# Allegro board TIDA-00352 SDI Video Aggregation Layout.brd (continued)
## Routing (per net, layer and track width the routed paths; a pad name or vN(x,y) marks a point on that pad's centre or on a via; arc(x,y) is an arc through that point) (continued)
I2C_STATUS1: length 183.7
  TOP w0.254: U42.18 101.32,24.75 v1(101.97,25.4)
  L14_SIG3 w0.152: v1(101.97,25.4) 101.97,25.83 101.98,25.84 101.98,29.21 96.52,34.67 84.99,34.67 84.07,35.59 84.07,44.07 76.2,51.94 71.12,51.94 62.48,60.58 62.48,101.35 53.59,110.24 53.59,115.06 50.42,118.24 41.27,118.24 40.89,118.62 40.89,118.63 35.76,123.76 35.76,142.71 26.93,151.54 v1(17.53,151.54)
I2C_SYNCN: length 125.3
  TOP w0.254: U42.22 99.32,25.27 v1(98.68,25.91)
  L14_SIG3 w0.152: v1(44.31,110.72) 44.92,110.11 48.9,110.11 51.69,107.31 53.21,107.31 60.45,100.08 60.45,59.56 70.1,49.91 74.8,49.91 79.83,44.88 79.83,30.15 81.28,28.7 97.54,28.7 98.68,27.56 v1(98.68,25.91)
INA0N: length 76.9
  BOTTOM w0.114: v2(49.09,68.16) 48.69,67.76 48.69,65.58 53.64,60.63 56.1,60.63 70.13,46.61 103.47,46.61 107.59,50.73 107.59,50.9 107.59,51.09 107.74,51.23 108.09,51.23 108.24,51.38 108.24,51.54 108.24,51.73 108.38,51.88 108.74,51.88 108.88,52.03 108.88,52.19 108.88,52.38 109.03,52.53 109.38,52.53 109.56,52.7 109.56,52.7 109.77,52.91 109.77,54.49 C224.1
INA0N_CONNECTOR: length 2.5
  BOTTOM w0.254: v1(109.22,57.78) 109.22,55.24
INA0P: length 76.9
  BOTTOM w0.114: v2(48.09,68.16) 48.5,67.76 48.5,65.5 53.56,60.44 56.02,60.44 70.05,46.42 103.55,46.42 109.75,52.62 109.75,52.62 109.96,52.83 109.96,54.51 C222.1
INA0P_CONNECTOR: length 2.5
  BOTTOM w0.254: v1(110.49,57.78) 110.49,55.24
INA1N: length 61.7
  BOTTOM w0.114: C220.1 99.6,54.5 99.6,53.67 99.28,53.35 99.02,53.35 98.82,53.16 98.82,52.9 98.63,52.71 98.37,52.71 98.18,52.52 98.18,52.25 94.94,49.02 70,49.02 53.64,65.38 53.64,67.73 52.62,68.76 51.5,68.76 v2(51.09,69.16)
INA1N_CONNECTOR: length 2.5
  BOTTOM w0.254: v1(99.06,57.78) 99.06,55.24
INA1P: length 61.7
  BOTTOM w0.114: C218.1 99.79,54.5 99.79,53.59 95.02,48.83 69.92,48.83 53.45,65.3 53.45,67.66 52.54,68.57 51.5,68.57 v2(51.09,68.16)
INA1P_CONNECTOR: length 2.5
  BOTTOM w0.254: v1(100.33,57.78) 100.33,55.24
INA2N: length 45.5
  BOTTOM w0.114: C216.1 84.39,54.47 84.39,53.86 84.22,53.69 84.03,53.69 83.97,53.69 83.77,53.49 83.77,53.3 83.77,53.24 83.57,53.04 83.38,53.04 83.32,53.04 83.12,52.84 83.12,52.65 83.12,52.59 81.58,51.05 70.64,51.05 56.31,65.38 56.31,66.8 53.35,69.77 50.49,69.77 v2(50.09,70.16)
INA2N_CONNECTOR: length 2.5
  BOTTOM w0.254: v1(83.82,57.78) 83.82,55.24
INA2P: length 45.5
  BOTTOM w0.114: v2(50.09,69.16) 50.51,69.58 53.27,69.58 56.12,66.73 56.12,65.3 70.56,50.86 81.66,50.86 84.58,53.78 84.58,54.53 C214.1
INA2P_CONNECTOR: length 2.5
  BOTTOM w0.254: v1(85.09,57.78) 85.09,55.24
INA3N: length 33.3
  BOTTOM w0.114: C212.1 74.2,54.5 74.2,53.73 73.63,53.16 73.29,53.16 73.16,53.29 72.83,53.29 72.7,53.16 71.91,53.16 71.62,53.45 71.62,53.64 71.62,53.79 71.47,53.94 71.13,53.94 64.6,60.47 64.6,61.64 54.48,71.75 51.5,71.75 v2(51.09,72.16)
INA3N_CONNECTOR: length 2.5
  BOTTOM w0.254: v1(73.66,57.78) 73.66,55.24
INA3P: length 33.3
  BOTTOM w0.114: C210.1 74.39,54.5 74.39,53.65 73.71,52.97 71.83,52.97 64.41,60.39 64.41,61.56 54.4,71.56 51.5,71.56 v2(51.09,71.16)
INA3P_CONNECTOR: length 2.5
  BOTTOM w0.254: v1(74.93,57.78) 74.93,55.24
JTAG_LS_EN: length 5.6
  BOTTOM w0.254: R270.2 53.95,12.83 53.92,12.86 R647.2 51.02,12.86 50.34,13.54 v1(50.34,14.61)
JTAG_LS_VCCB: length 6.7
  TOP w0.254: v1(55.5,10.64) 55.5,10.11 55.54,10.07 U40.19
  L3_SIG2 w0.152: v1(60.07,11.89) 58.83,10.64 v1(55.5,10.64)
JTAG_LS_VCCB_3V: length 1.2
  BOTTOM w0.254: R269.2 JMP62.2
LOSA: length 127.4
  L3_SIG2 w0.152: v2(43.09,72.16) 42.55,71.61 42.55,67.06 47.12,62.48 56.85,62.48 63.58,55.75 79.5,55.75 89.47,45.78 89.47,35.24 88.52,34.29 87.38,34.29 86.36,33.27 86.36,11.18 88.14,9.4 88.14,4.95 89.15,3.94 90.93,3.94 91.57,4.57 91.57,5.08 92.52,6.03 99.63,6.03 JMP48.1
  BOTTOM w0.254: R276.1 100.65,12.19 99.69,11.24 99.69,7.18 100.65,6.22 R273.1 JMP48.1
LOSA_G: length 26.6
  L14_SIG3 w0.152: v1(100.71,7.37) 91.01,17.07 91.01,19.08 89.85,20.24 v1(80.58,20.24)
LOSB: length 127.5
  L14_SIG3 w0.152: v2(44.09,77.16) 43.65,77.6 43.08,77.6 42.69,77.99 42.69,79.33 42.97,79.62 51.21,79.62 51.56,79.27 51.56,64.71 62.5,53.77 62.5,19.29 65.53,16.26 73.66,16.26 83.94,5.98 84.83,5.98 85.47,5.33 85.47,4.84 86.34,3.98 97.19,3.98 98.17,4.95
  BOTTOM w0.254: R283.1 98.17,10.67 97.28,9.78 97.28,7.05 98.11,6.22 R279.1 98.17,4.95
LOSB_G: length 26.9
  L14_SIG3 w0.152: v1(76.64,20.24) 77.32,19.56 85.98,19.56 v1(98.17,7.37)
LS_EN_FETD: length 13.8
  TOP w0.254: Q100.3 122.68,16.97 122.94,17.23 v1(123.44,17.23)
  L3_SIG2 w0.152: v1(123.44,17.23) 123.44,18.31 123.52,18.39 123.52,22.91 119.76,26.67 v1(118.49,26.67)
LS_OK_IN_A_CONNECTOR: length 205.9
  TOP w0.254: JMP61.3 84.2,5.97
  L3_SIG2 w0.152: JMP61.3 84.2,5.97 81.01,9.16 81.01,33.89 82.32,35.2 83.72,35.2 88.14,39.62 88.52,40.01 88.52,45.59 78.87,55.24 62.99,55.24 56.77,61.47 46.99,61.47 41.53,66.93 41.53,68.59 v2(42.09,69.16)
  L14_SIG3 w0.152: v1(118.11,57.78) 118.11,54.4 115.35,51.64 115.35,30.44 120.02,25.78 120.02,14.73 122.3,12.45 122.3,11.56 121.28,10.54 121.28,10.53 114.27,3.52 85.64,3.52 JMP61.3
  BOTTOM w0.254: R532.1 84.26,12.19 83.69,11.62 83.69,10.1 84.26,9.53 R619.1 84.33,8.89 83.57,8.13 83.57,6.79 84.14,6.22 R254.2 JMP61.3
LS_OK_IN_B_CONNECTOR: length 209.9
  L3_SIG2 w0.152: v1(118.11,69.22) 116.59,70.74 98.42,70.74 89.28,79.88 42.93,79.88 42.55,79.5 42.55,78.87 42.8,78.61 43.23,78.61 43.68,78.16 v2(44.09,78.16)
  L14_SIG3 w0.152: v1(118.11,69.22) 118.87,69.98 121.92,69.98 122.56,69.34 122.56,62.48 121.41,61.34 121.41,56.01 116.95,51.55 116.95,37.85 116.97,37.83 116.97,30.48 120.99,26.46 120.99,15.4 123.27,13.12 123.27,11.11 114.74,2.59 102.92,2.59 101.31,0.98 81.71,0.98 80.68,2.01 80.68,2.82 81.66,3.8 JMP61.5
  BOTTOM w0.254: JMP61.5 R255.2 81.6,6.22 81.03,6.79 81.03,8.95 81.6,9.53 ; 81.6,9.53 81.03,10.1 81.03,11.75 81.6,12.32 R533.1 ; 81.6,9.53 R620.1
LS_OK_OUT_A_CONNECTOR: length 214.1
  L3_SIG2 w0.152: 84.2,2.41 85.18,1.44 102.78,1.44 110.11,8.76 114.3,8.76 114.72,9.18 114.73,9.18 114.99,9.44 114.99,9.8 114.94,9.85 114.94,14.1 111.89,17.14 111.89,25.53 110.46,26.95 110.46,32.31 110.74,32.59 110.74,39.78 109.86,40.66 109.86,49.38 112.8,52.32 116.59,52.32 120.65,56.39 v1(120.65,57.78) 121.16,58.29 121.16,72.64 117.02,76.78 102.03,76.78 94.23,84.58 v1(86.49,84.58) ; v2(43.09,71.16) 43.55,71.62 43.55,73.19 43.92,73.57 52.16,73.57 v2(52.27,73.68) 62.12,73.68 62.87,74.42 v1(86.49,74.42)
  L14_SIG3 w0.152: v1(86.49,74.42) v1(86.49,84.58)
  BOTTOM w0.254: 84.2,2.41 85.47,3.68 85.47,9.91 85.85,10.29 R286.1 R274.1
LS_OK_OUT_A_G: length 21.2
  L14_SIG3 w0.152: v1(87.07,13.34) 82.12,18.29 70.72,18.29 v1(68.77,20.24)
  BOTTOM w0: v1(87.07,13.34) R274.2
LS_OK_OUT_B_CONNECTOR: length 211.6
  L3_SIG2 w0.152: v1(54.48,82.42) 66.42,82.42 67.06,81.79 91.57,81.79 101.09,72.26 118.87,72.26 120.65,70.48 v1(120.65,69.22) ; v2(43.09,75.16) 43.58,74.68 v1(54.33,74.68)
  L14_SIG3 w0.152: v1(54.33,74.68) 54.33,75.11 54.48,75.27 v1(54.48,82.42) ; JMP61.6 82.64,1.44 101.12,1.44 102.74,3.06 114.03,3.06 114.05,3.05 114.55,3.05 122.02,10.52 122.81,11.3 122.81,12.93 120.52,15.21 120.52,26.04 116.49,30.06 116.49,51.85 120.02,55.37 120.02,68.58 v1(120.65,69.22)
  BOTTOM w0.254: JMP61.6 80.39,3.68 80.39,6.35 79.88,6.86 R287.1 R277.1
LS_OK_OUT_B_G: length 16.5
  L14_SIG3 w0.152: v1(64.83,20.24) 67.41,17.65 74.3,17.65 v1(78.49,13.46)
MAIN_/RST: length 8.1
  L3_SIG2 w0.152: v1(76.34,107.57) 77.48,107.57 78.99,109.09 v1(78.99,112.39)
  BOTTOM w0.254: R243.2 v1(76.34,107.57)
MAIN_/RST_B: length 2.7
  BOTTOM w0.254: U38.4 77.4,113.34 77.6,113.54 R259.1
MAIN_/RST_C:
  vias: v1(77.4,114.51)
MAIN_/RST_L:
  vias: v1(77.47,116.15)
MAIN_RESET: length 22.8
  L3_SIG2 w0.152: v1(70.48,107.57) 70.48,106.43 69.5,105.44 64.86,105.44 63.01,107.29 63.01,108.44 58.42,113.03 58.42,114.87 v1(56.91,116.38)
  BOTTOM w0.254: v1(56.91,116.38) 56.91,117.61 R724.1
MAIN_RESET_HS: length 8.1
  BOTTOM w0.254: R243.1 R244.1 R241.2 ; R243.1 72.64,107.57 72.64,107.57 R486.1 ; R243.1 U36.4
MAIN_RST: length 3
  BOTTOM w0.254: U37.3 R244.2 74.42,109.88 R258.2
MAIN_RST_B: length 1.6
  BOTTOM w0.254: U38.6 75.5,111.38 75.56,111.32 R258.1
MAIN_RST_C:
  vias: v1(75.5,114.51)
MAIN_RST_DIR: length 5.2
  BOTTOM w0.254: v1(75.95,103.38) R245.2 75.95,105.11 75.75,105.31 74.07,105.31 73.8,105.04 U36.5
MAIN_RST_L:
  vias: v1(75.51,116.15)
MAIN_RST_SIGNAL: length 6.4
  BOTTOM w0.254: R466.2 U37.4 78.74,110.03 79.1,110.38 R465.2 79.1,111.25 79.53,111.69 79.53,111.96 v1(81.1,113.54)
MDC: length 85.2
  L14_SIG3 w0.152: 43.61,75.62 v2(43.59,75.64) 38.8,75.64 18.6,55.44 18.6,13.65 20.12,12.12 22.92,12.12 23.62,12.83 25.21,12.83 v1(25.84,12.2)
  BOTTOM w0.152: R294.1 43.59,76.1 v2(43.59,75.64)
  BOTTOM w0.254: R289.1 25.84,13.25 v1(25.84,12.2)
MDC_B2B_CON: length 140.3
  L3_SIG2 w0.152: v1(74.93,64.14) 74.32,64.74 64.29,64.74 63.37,65.66 v1(58.17,65.66)
  L14_SIG3 w0.152: v1(58.17,65.66) 58.17,82.68 57.4,83.44 27.56,83.44 9.91,65.79 9.91,24.38 11.43,22.86 11.43,21.72 13.08,20.07 13.08,17.79 v1(13.6,17.27)
MDC_BYPASS: length 20.9
  L14_SIG3 w0.152: v1(24.69,12.2) 24.16,11.67 15.3,11.67 9.65,17.31 9.65,18.39 8.87,19.18 8.26,19.18 v1(7.87,19.56)
MDC_CON: length 3.3
  BOTTOM w0.254: JMP50.2 R291.1 R299.1
MDC_DUT:
  vias: v2(44.09,76.16)
MDC_HDR: length 17.5
  L14_SIG3 w0.152: 4.57,12.32 3.17,13.72 3.17,19.05 4.44,20.32 8.89,20.32 9.83,19.38 11.87,19.38 v1(12.31,19.81)
MDC_LS_BY: length 13.2
  L14_SIG3 w0.152: v1(18.16,7.11) 17.73,7.11 14.55,10.29 14.55,11.07 9.74,15.88 v1(9.02,15.88)
MDC_OUT_POST_LS: length 102.5
  TOP w0.254: K2.3 v1(13.6,18.54)
  L3_SIG2 w0.152: v1(13.6,18.54) 13.6,19.67 12.7,20.57 12.7,27.37 16.13,30.8 16.13,81.09 19.62,84.58 42.74,84.58 44.2,83.12 v1(44.2,81.53)
  BOTTOM w0.114: v1(44.2,81.53) 44.2,80.9 43.56,80.26 R294.2
MDC_POST_LS: length 2.1
  BOTTOM w0.254: v1(25.84,11.05) 25.84,10.55 26.09,10.29 U43.3
MDC_PRE_LS: length 15.3
  BOTTOM w0.254: R637.2 19.3,3.43 20.83,1.91 25.63,1.91 26.09,2.37 U43.18 v1(26.09,4.58) 26,4.67 26,4.81 25.67,5.14 24.82,5.14 24.42,4.74 R307.1
MDC_USB: length 7.7
  TOP w0.254: J101.12 v1(17.98,10.98)
  BOTTOM w0.254: R308.1 20.44,8.64 18.45,10.64 18.32,10.64 v1(17.98,10.98)
MDIO: length 85
  L14_SIG3 w0.152: v1(26.87,12.2) 25.1,13.97 23.75,13.97 22.99,13.21 20.57,13.21 19.68,14.1 19.68,54.99 39.37,74.68 44.46,74.68 44.61,74.83 v2(44.61,75.64)
  BOTTOM w0.152: R292.1 44.58,76.1 44.58,75.68 v2(44.61,75.64)
  BOTTOM w0.254: R288.2 26.87,13.25 v1(26.87,12.2)
MDIO_B2B_CON: length 139.4
  L3_SIG2 w0.152: v1(57.91,64.77) 63.5,64.77 64.14,64.14 v1(72.39,64.14)
  L14_SIG3 w0.152: v1(13.73,15.11) 14.35,15.73 14.35,19.49 11.94,21.91 11.94,23.11 10.41,24.64 10.41,65.53 27.79,82.91 57.17,82.91 57.66,82.42 57.66,65.46 57.91,65.2 v1(57.91,64.77)
MDIO_B2B_R: length 10.3
  L3_SIG2 w0.152: v1(15.48,13.84) 16,14.36 16,16.62 v1(15.35,17.27)
  BOTTOM w0.254: Q103.3 R641.2 17.43,19.35 v1(15.35,17.27)
MDIO_B2B_R_INV: length 4.5
  BOTTOM w0.254: Q103.1 21.64,22.29 21.65,22.29 R642.2 Q104.3
MDIO_B2B_RELAY: length 130.6
  TOP w0.254: SW11.15 v1(114.55,9.62)
  L3_SIG2 w0.152: v1(92.84,26.8) 91.82,25.78 88.14,25.78 v1(87.76,26.16) ; v1(74.04,26.16) 74.04,19.05 72.26,17.27 v1(72.26,6.48)
  L14_SIG3 w0.152: v1(114.55,9.62) 103.16,9.62 99.06,13.72 99.06,18.8 98.3,19.56 96.9,19.56 96.27,18.92 93.73,18.92 92.84,19.81 v1(92.84,26.8) ; v1(87.76,26.16) v1(74.04,26.16) ; v1(72.26,6.48) 71.88,6.86 44.96,6.86 36.53,15.29 36.53,18.1 33.41,21.21 31.24,21.21 v1(29.21,23.24)
  BOTTOM w0.254: v1(29.21,23.24) Q104.1
MDIO_BYPASS: length 26.5
  L14_SIG3 w0.152: v1(7.87,14.73) 13.84,8.76 15.24,8.76 17.53,6.48 20.83,6.48 21.84,7.49 24.26,7.49 27.3,10.54 27.3,11.49 v1(28.01,12.2)
MDIO_CON: length 3.3
  BOTTOM w0.254: R298.1 R290.1 JMP50.4
MDIO_CON_R: length 17.3
  L3_SIG2 w0.152: v1(10.55,19.81) 10.99,19.38 10.99,14.15 v1(10.68,13.84)
  BOTTOM w0.254: R644.2 2.57,23.75 Q101.3 3.95,22.34 4.95,21.34 8.25,21.34 9.78,19.81 v1(10.55,19.81)
MDIO_CON_R_INV: length 8.3
  BOTTOM w0.254: Q101.1 6,24.7 6.95,23.75 Q102.3 8.53,22.72 9.4,21.84 R645.2
MDIO_CON_RELAY: length 147.4
  TOP w0.254: SW11.17 v1(115.82,9.62)
  L3_SIG2 w0.152: v1(72.9,26.8) 72.9,22.48 72.14,21.72 72.14,18.92 71.5,18.29 v1(71.5,5.46)
  L14_SIG3 w0.152: v1(12.19,24.64) 17.53,19.3 v1(18.03,19.3) ; v1(115.82,9.62) 115.37,9.16 101.55,9.16 91.47,19.24 91.47,20.66 90.04,22.09 90.04,24.77 89.41,25.4 v1(89.41,26.8) v1(72.9,26.8) ; v1(71.5,5.46) 70.9,6.06 44.74,6.06 36.07,14.73 36.07,17.91 34.67,19.3 v1(20.83,19.3)
  BOTTOM w0.152: v1(20.83,19.3) v1(18.03,19.3)
  BOTTOM w0.254: Q102.1 11.23,24.7 11.29,24.64 v1(12.19,24.64)
MDIO_DUT:
  vias: v2(45.09,76.16)
MDIO_HDR: length 9
  BOTTOM w0.254: v1(12.43,12.57) 9.64,9.78 JMP103.1
MDIO_LS: length 46.8
  L14_SIG3 w0.508: JMP77.2 36.32,5.84 33.4,2.92 26.29,2.92 25.44,3.77 v1(25.44,4.58) 23.08,4.58 22.92,4.74 v1(22.48,4.74) 22.48,5.33 22.48,5.33 v1(22.48,5.77) ; v1(22.48,5.77) 16.46,5.77 16,6.22 13.87,6.22 5.97,14.12 v1(5.97,14.73) v1(5.97,19.56) ; v1(22.48,5.77) 22.78,6.07 22.78,6.08 v1(23.55,6.84)
  BOTTOM w0.254: U43.19 v1(25.44,4.58)
MDIO_LS_BY: length 16.1
  L14_SIG3 w0.152: v1(9.02,18.41) 9.02,17.26 15.3,10.97 16.21,10.97 19.3,7.88 v1(19.3,7.11)
MDIO_LS_EN: length 4.2
  BOTTOM w0.254: U43.10 v1(30.64,7.87) 32,7.87 R305.1 R638.2
MDIO_OUT_POST_LS: length 110.2
  TOP w0.254: K1.4 v1(13.73,13.84)
  L3_SIG2 w0.152: v1(44.96,81.53) 44.96,83.44 43.05,85.34 19.3,85.34 15.37,81.41 15.37,31.37 11.68,27.69 11.68,15.89 v1(13.73,13.84)
  BOTTOM w0.114: v1(44.96,81.53) 44.96,80.77 44.55,80.37 R292.2
MDIO_POST_LS: length 2.1
  BOTTOM w0.254: U43.4 26.74,10.42 26.87,10.55 v1(26.87,11.05)
MDIO_PRE_LS: length 19.2
  BOTTOM w0.254: R306.1 26.06,5.74 26.74,5.06 v1(26.74,4.58) U43.17 26.74,1.85 26.04,1.14 20.07,1.14 18.16,3.05 R309.2
MDIO_USB: length 8.9
  TOP w0.254: J101.14 v1(18.98,10.99)
  BOTTOM w0.254: v1(18.98,10.99) 18.44,11.54 17.75,11.54 17.02,10.81 R309.1
MOD_DEF0_MODULE_DETECT: length 34.5
  L3_SIG2 w0.152: v1(29.04,33.53) 28.74,33.22 27.97,33.22 27.3,32.55 27.3,29.84 28.57,28.57 30.23,28.57 32.89,25.91 35.56,25.91 36.2,25.27 47.88,25.27 49.52,23.63 v1(52.89,23.63)
  BOTTOM w0.254: v1(52.89,23.63) 53.74,23.63 53.75,23.62 R559.2
MOD_DEF1_SCL: length 38.9
  L3_SIG2 w0.152: v1(29.04,34.33) 26.04,37.34 26.04,41.91 27.3,43.18 28.45,43.18 29.72,44.45 46.74,44.45 48.64,42.55 48.64,39.75 48.26,39.37 JMP105.1
  BOTTOM w0.254: R563.2 JMP105.1
MOD_DEF2_SDA: length 29
  L3_SIG2 w0.152: v1(29.04,35.13) 27.98,36.2 27.98,40.93 30.99,43.94 45.21,43.94 JMP105.3
  BOTTOM w0.254: R562.2 JMP105.3
MODE_SEL/REFCLK_SEL: length 192.5
  TOP w0.254: v1(109.47,10.16) SW11.7
  L3_SIG2 w0.152: v1(109.47,10.16) 110.28,10.97 110.28,11.75 110.46,11.94 112.17,11.94 112.52,11.58 112.52,9.68 112.67,9.53 113.77,9.53 114.3,10.06 114.3,13.97 111.43,16.84 111.43,24.97 110.01,26.39 110.01,32.5 110.21,32.7 110.21,39.27 109.22,40.26 109.22,49.78 112.27,52.83 116.2,52.83 120.14,56.77 120.14,70.1 118.49,71.75 100.46,71.75 91.31,80.9 41.66,80.9 40.64,79.88 40.64,75.95 41.02,75.57 41.68,75.57 v2(42.09,75.16)
  BOTTOM w0.254: R462.1 119.63,22.1 121.16,20.57 121.16,16.13 119.56,14.53 111.62,14.53 110.17,13.08 R618.1 109.6,12.45 110.11,11.94 110.11,10.79 v1(109.47,10.16)
MODULE_DETECT_D: length 8.8
  BOTTOM w0.254: Q12.3 49.68,18.64 49.15,19.18 49.15,24.86 v1(50.1,25.81)
MODULE_DETECT_G: length 6
  BOTTOM w0.254: R564.2 Q12.1 51.91,19.59 50.69,20.81 Q11.3
MODULE_DETECT_L:
  vias: v1(52.2,25.81)
Net_520: length 1.8
  TOP w0.254: v1(90.42,18.03) 90.42,18.16 89.96,18.62 88.91,18.62
Net_521: length 1.6
  TOP w0.254: v1(90.42,19.05) 90.2,19.27 88.91,19.27
Net_806:
  vias: v1(14.41,134.29)
OUTA0N: length 75
  TOP w0.114: U1.A7 45.5,67.76 45.5,63.21 49.15,59.56 58.46,59.56 71.63,46.39 98.69,46.39 104.86,52.57 104.86,53.22 105.13,53.49 R572.1
OUTA0N_CONNECTOR: length 3.8
  TOP w0.254: R572.2 J72.K27
OUTA0P: length 75
  TOP w0.114: R571.1 104.67,53.24 104.67,52.64 98.61,46.58 71.7,46.58 58.53,59.75 49.23,59.75 45.69,63.29 45.69,63.91 45.88,64.1 45.88,64.37 45.69,64.56 45.69,64.82 45.88,65.02 45.88,65.28 45.69,65.48 45.69,65.74 45.88,65.93 45.88,66.2 45.69,66.39 45.69,66.65 45.88,66.85 45.88,67.11 45.69,67.3 45.69,67.76 U1.A6
OUTA0P_CONNECTOR: length 3.8
  TOP w0.254: R571.2 J72.K26
OUTA1N: length 63.5
  TOP w0.114: R570.1 94.97,53.49 94.72,53.24 94.72,51.78 90.93,47.99 72.36,47.99 58.86,61.49 49.07,61.49 46.5,64.07 46.5,68.76 U1.B6
OUTA1N_CONNECTOR: length 3.8
  TOP w0.254: R570.2 J72.K19
OUTA1P: length 63.5
  TOP w0.114: R569.1 94.53,53.22 94.53,51.85 90.86,48.18 72.44,48.18 58.94,61.68 49.15,61.68 46.69,64.15 46.69,64.93 46.93,65.18 46.93,65.39 46.69,65.63 46.69,65.85 46.93,66.09 46.93,66.3 46.69,66.55 46.69,66.76 46.93,67 46.93,67.22 46.69,67.46 46.69,68.76 U1.B5
OUTA1P_CONNECTOR: length 3.8
  TOP w0.254: R569.2 J72.K18
OUTA2N: length 56.7
  TOP w0.114: U1.C5 47.5,69.76 47.5,64.44 47.7,64.24 47.71,64.24 49.34,62.61 60.06,62.61 72.87,49.8 87.53,49.8 89.64,51.9 89.64,53.24 89.89,53.49 R568.1
OUTA2N_CONNECTOR: length 3.8
  TOP w0.254: R568.2 J72.K15
OUTA2P: length 56.6
  TOP w0.114: R567.1 89.44,53.23 89.44,51.97 87.45,49.99 72.95,49.99 60.13,62.8 49.42,62.8 47.79,64.43 47.78,64.43 47.69,64.52 47.69,64.79 47.94,65.04 47.94,65.25 47.69,65.5 47.69,65.71 47.94,65.96 47.94,66.17 47.69,66.41 47.69,66.62 47.94,66.87 47.94,67.08 47.69,67.33 47.69,69.76 U1.C4
OUTA2P_CONNECTOR: length 3.8
  TOP w0.254: R567.2 J72.K14
OUTA3N: length 41.4
  TOP w0.114: R566.1 79.73,53.49 79.66,53.49 79.47,53.3 79.47,52.15 78.84,51.52 73.9,51.52 70.53,54.89 70.31,54.89 66.87,58.33 66.87,58.99 53.3,72.56 49.5,72.56 U1.E3
OUTA3N_CONNECTOR: length 3.8
  TOP w0.254: R566.2 J72.K7
OUTA3P: length 41.4
  TOP w0.114: U1.F3 49.5,72.75 51.51,72.75 51.69,72.94 51.96,72.94 52.15,72.75 52.42,72.75 52.6,72.94 52.88,72.94 53.06,72.75 53.38,72.75 67.06,59.07 67.06,58.41 70.39,55.08 70.61,55.08 73.98,51.71 78.77,51.71 79.28,52.23 79.28,53.3 79.09,53.49 R565.1
OUTA3P_CONNECTOR: length 3.8
  TOP w0.254: R565.2 J72.K6
OUTA4N: length 34.4
  TOP w0.114: U1.H3 49.5,75.56 50.39,75.56 50.67,75.84 50.67,76.42 50.78,76.53 52.44,76.53 52.58,76.4 52.9,76.4 53.04,76.53 53.36,76.53 53.5,76.4 53.81,76.4 53.95,76.53 54.27,76.53 54.41,76.4 54.73,76.4 54.87,76.53 76.85,76.53 76.86,76.53 76.88,76.53 79.26,74.14 79.26,72.48 R580.1
OUTA4P: length 34.4
  TOP w0.114: R579.1 79.45,72.52 79.45,74.22 76.96,76.72 76.94,76.72 76.93,76.73 50.7,76.73 50.47,76.5 50.47,75.92 50.31,75.76 49.5,75.76 U1.J3
OUTA5N: length 52.3
  TOP w0.114: U1.K4 47.69,77.56 47.69,80.55 48.69,81.55 48.93,81.55 49.19,81.3 49.39,81.3 49.65,81.55 49.85,81.55 50.1,81.3 50.31,81.3 50.56,81.55 50.76,81.55 51.02,81.3 51.22,81.3 51.48,81.55 83.41,81.55 89.44,75.53 89.44,72.5 R578.1
OUTA5P: length 52.2
  TOP w0.114: R577.1 89.63,72.5 89.63,75.6 83.49,81.74 48.61,81.74 47.5,80.63 47.5,77.56 U1.K5
OUTA6N: length 60.2
  TOP w0.114: U1.L5 46.69,78.56 46.69,79.55 46.82,79.69 46.88,79.69 47.02,79.82 47.02,80.01 46.88,80.14 46.82,80.14 46.69,80.28 46.69,80.47 46.82,80.6 46.88,80.6 47.02,80.73 47.02,80.92 46.88,81.06 46.82,81.06 46.69,81.19 46.69,81.5 48.95,83.76 87.04,83.76 94.49,76.31 94.49,72.47 R576.1
OUTA6P: length 60.1
  TOP w0.114: U1.L6 46.5,78.56 46.5,81.58 48.87,83.95 87.12,83.95 94.68,76.39 94.68,72.53 R575.1
OUTA7N: length 70.8
  TOP w0.114: U1.M6 45.69,79.56 45.69,79.57 45.69,79.98 45.82,80.11 45.87,80.11 46,80.24 46,80.43 45.87,80.57 45.82,80.57 45.69,80.7 45.69,80.89 45.82,81.02 45.87,81.02 46,81.16 46,81.35 45.87,81.48 45.82,81.48 45.69,81.62 45.69,82.38 48.98,85.67 92.58,85.67 104.69,73.56 104.69,72.51 R574.1
OUTA7P: length 70.8
  TOP w0.114: U1.M7 45.5,79.56 45.5,82.46 48.9,85.86 92.65,85.86 104.88,73.63 104.88,72.49 R573.1
P_BIAS: length 4.9
  TOP w0.254: R781.1 v1(12.3,141.44) ; R780.1 v1(12.3,143.06)
  BOTTOM w0.254: C691.2 R779.2 R778.1 12.19,140.84 12.3,140.95 v1(12.3,141.44) v1(12.3,143.06)
PDN: length 87.6
  TOP w0.254: v1(17.54,148.14) 17.88,147.8 17.88,147.73 17.91,147.69 U100.43
  L3_SIG2 w0.152: v1(17.54,148.14) 17.94,148.54 18.6,148.54 20.89,146.25 25.72,146.25 26.55,145.41 30.86,145.41 35.05,141.22 35.05,123.06 37.72,120.4 59.44,120.4 66.42,113.41 v1(66.42,111.38)
  BOTTOM w0.254: R728.2 66.42,110.53 v1(66.42,111.38) 66.37,111.43 R729.2 ; R717.2 17.59,155.44 16.94,154.79 16.94,149.94 16.97,149.91 16.97,149.63 17.54,149.06 v1(17.54,148.14)
PDN_/RST: length 8
  TOP w0.254: v1(68.04,110.47) 64.98,110.47 U108.1
  L3_SIG2 w0.152: v1(68.04,110.47) 67.6,110.03 67.6,106.36 v1(68.06,105.9)
PDN_/RST_B: length 1.3
  BOTTOM w0.254: U109.6 R730.1
PDN_RESET: length 5.1
  BOTTOM w0.254: v1(62.56,112.34) 60.4,112.34 R726.2 R727.2
PDN_RESET_AND: length 1.5
  BOTTOM w0.254: v1(57.86,113.76) 57.86,112.32 R727.1
PDN_RST: length 8.2
  TOP w0.254: U108.3 64.99,112.38 v1(68.04,112.38)
  L3_SIG2 w0.152: v1(68.06,107.8) 68.71,108.45 68.71,111.71 v1(68.04,112.38)
PDN_RST_B: length 1.3
  BOTTOM w0.254: U109.4 R731.1
PDN_SWITCH: length 13.2
  L3_SIG2 w0.152: v1(61.93,115.7) 61.93,116.25 60.45,117.73 v1(58.18,117.73) v1(55.87,117.73)
  BOTTOM w0.254: v1(61.93,115.7) 59.18,112.95 R726.1 ; v1(55.87,117.73) 56,117.59 v1(56,116.33)
PDTRXA_N: length 125.3
  TOP w0.254: SW11.1 v1(105.66,10.16)
  L3_SIG2 w0.152: v1(105.66,10.16) 102.36,10.16 100.2,12.32 100.2,35.18 96.39,38.99 96.39,47.5 87.12,56.77 63.86,56.77 56.49,64.14 48.12,64.14 v2(44.09,68.16)
  BOTTOM w0.254: R459.1 119.13,17.4 118.49,16.76 108.08,16.76 106.3,14.99 106.3,10.73 105.73,10.16 v1(105.66,10.16)
PDTRXB_N: length 136.1
  TOP w0.254: v1(106.93,10.16) SW11.3
  L3_SIG2 w0.152: v2(48.09,76.16) 48.5,76.57 85.97,76.57 94.41,68.12 94.41,51.77 104.98,41.2 104.98,29.13 105.16,28.96 105.16,12.45 106.93,10.67 v1(106.93,10.16)
  BOTTOM w0.254: R460.1 119.63,19.56 120.02,19.18 120.02,17.02 119.13,16.13 108.97,16.13 107.57,14.73 107.57,10.79 v1(106.93,10.16)
PRBS_PASS: length 129.8
  L14_SIG3 w0.152: JMP48.5 95.1,5.49 94.81,5.49 93.82,6.48 84.2,6.48 73.66,17.02 65.53,17.02 63.36,19.19 63.36,27.29 66.42,30.35 66.42,50.55 58.42,58.55 58.42,58.93 52.96,64.39 52.96,78.87 51.18,80.64 42.29,80.64 41.66,80.01 41.66,77.02 41.92,76.75 42.5,76.75 v2(43.09,76.16)
  BOTTOM w0.254: JMP48.5 R275.1 95.57,6.22 94.74,7.05 94.74,10.03 95.63,10.92 R285.1
PRBS_PASS_G: length 28.3
  L14_SIG3 w0.152: v1(95.63,7.37) 84.07,18.92 74.02,18.92 v1(72.7,20.24)
PRBSEN: length 139.7
  TOP w0.254: v1(110.74,10.16) SW11.9
  L3_SIG2 w0.152: v2(43.09,69.16) 43.5,69.57 44.29,69.57 44.5,69.77 44.5,71.42 44.7,71.63 51.56,71.63 57.33,65.86 57.33,63.95 63.92,57.35 87.55,57.35 102.69,42.22 102.69,30.66 104.65,28.7 104.65,11.43 105.28,10.79 105.65,10.79 107.2,9.25 109.87,9.25 110.74,10.12 v1(110.74,10.16)
  BOTTOM w0.254: v1(110.74,10.16) 111.38,10.79 111.38,12.83 112.52,13.97 120.27,13.97 122.3,16 122.3,20.95 119.89,23.37 R463.1
PRI_EN: length 3.6
  BOTTOM w0.254: R770.2 v1(9.21,165.28) ; R770.2 R772.1 ; R770.2 9.2,166.81 R773.2
PRI_LED:
  vias: v1(9.02,160.21)
PRI_OSC_EN: length 222.7
  TOP w0.254: U42.6 100.82,17.8 v1(101.47,17.14)
  L3_SIG2 w0.152: v1(7.11,166.81) 8.08,166.81 v1(9.21,167.94) 12.9,164.25 12.9,163.88 v1(13.21,163.58)
  L14_SIG3 w0.152: v1(13.21,163.58) 13.21,141.22 10.92,138.94 10.92,131.95 10.54,131.57 10.54,121.54 12.71,119.37 v1(17.78,119.37) 18.66,118.49 19.51,118.49 28.45,109.55 28.45,105.41 30.99,102.87 48.77,102.87 51.18,100.46 51.18,90.93 58.8,83.31 58.8,64.77 58.74,64.71 58.74,59.5 58.93,59.31 58.93,58.8 69.34,48.39 74.04,48.39 76.07,46.35 76.07,39.75 76.58,39.24 76.58,29.59 78.92,27.25 95.05,27.25 95.63,26.67 95.63,23.62 96.56,22.7 97.57,22.7 98.17,22.1 98.17,20.45 v1(101.47,17.14)
PRI_REF_IN_N: length 6.3
  TOP w0.114: R785.2 10.03,142 9.87,142.16 4.96,142.16 4.95,142.14 4.75,142.14 4.49,141.88 C693.1
PRI_REF_IN_N_SMP: length 3.2
  TOP w0.254: J104.1 R783.1 C693.2
PRI_REF_IN_P: length 6.3
  TOP w0.114: C692.1 4.49,142.6 4.75,142.34 4.87,142.34 4.88,142.35 9.87,142.35 10.03,142.5 R784.2
PRI_REF_IN_P_SMP: length 3.2
  TOP w0.254: C692.2 R782.1 J103.1
PRI_REFN: length 4.1
  TOP w0.114: R785.1 11.09,142 11.25,142.16 12.31,142.16 12.47,142 R781.2 13.02,142 13.18,142.16 13.77,142.16 13.93,142 U100.9
PRI_REFP: length 4.1
  TOP w0.114: R784.1 11.09,142.5 11.25,142.35 12.31,142.35 12.47,142.5 R780.2 13.02,142.5 13.18,142.35 13.77,142.35 13.93,142.5 U100.8
PRI_STDBY: length 3.5
  BOTTOM w0.254: R775.2 v1(12.08,161.18) R774.1 12.09,162.43 R771.2
PRI_XO: length 17.5
  TOP w0.254: R777.1 v1(10.84,143.51)
  BOTTOM w0.254: v1(10.84,143.51) 10.16,144.19 10.16,157.1 11.08,158.01 v1(11.08,159.88)
PRTAD0: length 120
  L3_SIG2 w0.152: JMP101.1 74.04,5.89 76.2,8.05 76.2,27.74 76.71,28.24 76.71,34.09 78.74,36.12 83.34,36.12 87.55,40.33 87.55,44.92 78.24,54.23 62.09,54.23 56.5,59.82 46.74,59.82 39.37,67.18 39.37,70.87 40.13,71.63 41.56,71.63 v2(42.09,72.16)
  BOTTOM w0.254: JMP101.1 74.04,12.32
PRTAD1: length 90.4
  TOP w0.254: SW12.7 v1(69.98,9.62)
  L14_SIG3 w0.152: v2(43.09,74.16) 43.5,73.75 43.5,73.18 44.06,72.62 47.21,72.62 47.55,72.28 47.55,59.51 52.2,54.86 52.2,44.07 54.1,42.16 55.32,42.16 56.01,41.48 56.01,31.32 56.77,30.56 56.77,11.43 60.74,7.45 67.84,7.45 69.62,9.24 69.62,9.26 v1(69.98,9.62)
  BOTTOM w0.254: v1(69.98,9.62) 69.98,12.32
PRTAD2: length 92.2
  TOP w0.254: SW12.5 v1(68.71,9.62)
  L14_SIG3 w0.152: v2(43.09,78.16) 43.55,78.62 45.59,78.62 46.61,77.6 47.75,77.6 49.54,75.81 49.54,59.68 53.59,55.63 53.59,45.97 56.46,43.1 57.71,43.1 58.29,42.52 58.29,11.8 61.72,8.37 67.46,8.37 v1(68.71,9.62)
  BOTTOM w0.254: v1(68.71,9.62) 68.71,12.32
PRTAD3: length 89.8
  TOP w0.254: 67.44,8.63 v1(67.44,9.62)
  L14_SIG3 w0.152: v1(67.44,9.62) 67.89,10.07 68.9,10.07 69.16,9.81 69.16,9.43 67.65,7.91 61.53,7.91 57.28,12.17 57.28,30.99 56.64,31.62 56.64,41.78 52.83,45.59 52.83,55.12 48.51,59.44 48.51,74.52 48.36,74.68 47.88,74.68 47.62,74.93 47.62,75.44 47.31,75.75 46.5,75.75 v2(46.09,76.16)
  BOTTOM w0.254: v1(67.44,9.62) 67.44,12.32
PRTAD4: length 87.9
  TOP w0.254: SW12.1 v1(66.17,9.62)
  L14_SIG3 w0.152: v1(66.17,9.62) 65.12,10.67 62.33,10.67 58.75,14.25 58.75,42.71 57.9,43.56 56.9,43.56 54.23,46.23 54.23,56.01 50.55,59.69 50.55,78.28 50.09,78.74 46.48,78.74 46.06,79.16 v2(44.09,79.16)
  BOTTOM w0.254: v1(66.17,9.62) 66.17,12.32
RATE_SEL_0: length 3.7
  BOTTOM w0.254: R560.2 v1(29.04,32.73) R795.1
RATE_SEL_1: length 3.7
  BOTTOM w0.254: R561.2 30.97,31.13 v1(29.04,31.13) 27.28,31.13 R796.1
REF_SEL: length 35.4
  TOP w0.254: SW16.1 v1(1.4,165.35) ; U100.6 v1(13.72,143.5)
  L3_SIG2 w0.152: v1(13.72,143.5) 13.72,144.65 10.92,147.45 10.92,152.53 2.92,160.53 2.92,163.83 v1(1.4,165.35)
  BOTTOM w0.254: R720.2 v1(1.4,165.35) ; v1(13.72,143.5) 13.34,143.89 12.06,143.89 11.43,144.53 R714.2
REFCLK0N: length 5.6
  BOTTOM w0.114: v2(41.09,79.16) 41.5,79.57 41.5,79.68 40.67,80.51 39.05,80.51 37.99,81.57 37.99,81.92 C197.1 C195.2
REFCLK0N_SMP: length 21.2
  TOP w0.254: J42.1 26.91,88.97 28.11,87.77 arc(28.33,87.23) 28.11,86.69 27.86,86.45 arc(27.86,85.37) 28.94,85.37 29.18,85.61 arc(30.26,85.61) 30.26,84.54 30.02,84.29 arc(30.02,83.22) 31.1,83.22 31.34,83.46 arc(31.88,83.68) 32.42,83.46 33.78,82.09 v2(37.26,82.09)
REFCLK0N_U0N: length 81.5
  TOP w0.114: U100.25 22.4,140.5 22.55,140.66 23.56,140.66 v1(23.88,140.34)
  L3_SIG2 w0.114: v1(20.1,91.19) 20.45,91.53 20.45,99.96 28.64,108.16 28.64,137.97 25.95,140.66 24.19,140.66 v1(23.88,140.34)
  BOTTOM w0.114: C195.1 37.82,83.09 37.73,83.19 26.06,83.19 20.29,88.95 R499.1 20.29,89.6 20.36,89.67 20.36,90.92 v1(20.1,91.19)
REFCLK0P: length 5.6
  BOTTOM w0.114: v2(42.09,79.16) 41.69,79.56 41.69,79.57 41.69,79.56 41.69,79.76 40.75,80.7 39.13,80.7 38.19,81.65 38.19,81.92 C191.1
REFCLK0P_SMP: length 21.2
  TOP w0.254: v2(38.92,82.09) 38.34,82.68 38.34,84.89 arc(38.11,85.43) 37.57,85.66 36.35,85.66 arc(35.59,86.42) 36.35,87.18 37.57,87.18 arc(38.34,87.94) 37.57,88.7 36.35,88.7 arc(35.59,89.47) 36.35,90.23 37.57,90.23 arc(38.11,90.45) 38.34,90.99 J41.1
REFCLK0P_U0P: length 81.8
  TOP w0.114: v1(23.88,141.17) 23.56,140.85 22.55,140.85 22.4,141 U100.26
  L3_SIG2 w0.114: v1(20.82,91.19) 20.82,91.6 20.7,91.72 20.7,99.82 28.83,107.95 28.83,138.05 26.03,140.85 24.19,140.85 v1(23.88,141.17)
  BOTTOM w0.114: C193.1 38.36,82.99 38.17,83.18 38.01,83.18 37.81,83.39 26.2,83.39 20.62,88.97 R498.1 20.62,89.6 20.55,89.67 20.55,90.92 v1(20.82,91.19)
REFCLK1N: length 5.6
  BOTTOM w0.114: v2(42.09,77.16) 42.5,77.57 42.5,82.33 C205.1
REFCLK1N_SMP: length 21.2
  TOP w0.254: v2(41.78,82.5) 41.78,85.67 42.4,86.29 arc(42.62,86.83) 42.4,87.37 41.82,87.95 arc(41.82,89.03) 42.9,89.03 43.48,88.45 arc(44.56,88.45) 44.56,89.52 43.97,90.11 arc(43.97,91.18) 45.05,91.18 45.64,90.6 arc(46.17,90.38) 46.71,90.6 47.24,91.14 47.24,93.28 47.23,93.3 J44.1
REFCLK1N_U1N: length 80
  TOP w0.114: U100.33 22.4,144.5 22.55,144.35 23.56,144.35 v1(23.88,144.67)
  L3_SIG2 w0.114: v1(23.88,144.67) 23.55,144.34 22.02,144.34 21.53,143.84 21.53,142.67 21.89,142.3 24.59,142.3 25.11,142.83 29.37,142.83 32.17,140.03 32.17,104.43 32.07,104.34 32.07,96.02 v1(31.81,95.76)
  BOTTOM w0.114: v1(31.81,95.76) 32.07,95.49 32.07,94.65 32,94.58 R497.1 32,93.94 32.26,93.69 32.28,93.69 42.33,83.63 C203.1
REFCLK1P: length 5.6
  BOTTOM w0.114: C201.2 42.69,82.32 42.69,77.56 v2(43.09,77.16)
REFCLK1P_SMP: length 21.2
  TOP w0.254: J43.1 56.12,88.86 54.35,87.1 50.58,87.1 arc(50.05,87.32) 49.82,87.86 49.82,87.97 arc(49.06,88.73) 48.3,87.97 48.3,87.86 arc(48.07,87.32) 47.54,87.1 46.89,87.1 43.43,83.64 v2(43.43,82.5)
REFCLK1P_U1P: length 79.7
  TOP w0.114: U100.32 22.4,144 22.55,144.16 23.56,144.16 v1(23.88,143.84)
  L3_SIG2 w0.114: v1(32.53,95.76) 32.26,96.02 32.26,104.26 32.36,104.36 32.36,140.11 29.45,143.02 25.03,143.02 24.51,142.49 21.97,142.49 21.72,142.75 21.72,143.76 22.1,144.15 23.57,144.15 v1(23.88,143.84)
  BOTTOM w0.114: v1(32.53,95.76) 32.26,95.49 32.26,94.65 32.34,94.58 R496.1 32.34,93.88 32.36,93.88 42.87,83.37 C201.1
REFCLK_SEL: length 7.1
  TOP w0.254: U64.15 102.93,21.61 102.93,21.6 U42.13
REFCLK_SEL_LS: length 3.1
  TOP w0.254: U64.6 117.49,21.61 v1(117.98,22.1)
REG_CAP: length 3.7
  TOP w0.254: U100.40 19.41,147.59 19.43,147.61 19.43,149.2 20.27,150.04 C684.1
RESET/PWR: length 62.3
  TOP w0.254: v1(17.14,145.67) 17.2,145.67 17.41,145.88 U100.44
  L3_SIG2 w0.152: v1(38.45,110.85) v1(38.45,112.76)
  L14_SIG3 w0.152: v1(17.14,145.67) 28.83,145.67 30.73,143.76 30.73,124.97 38.45,117.25 v1(38.45,112.76)
  BOTTOM w0.254: v1(17.14,145.67) 17.14,147.19 16.64,147.7 16.64,148.97 15.82,149.79 15.82,154.99 16.26,155.42 R718.2
RESET_N: length 68.6
  L3_SIG2 w0.152: v1(74.93,75.82) 62.48,75.82 62.23,75.57 47.5,75.57 v2(47.09,75.16)
  L14_SIG3 w0.152: v1(74.93,75.82) 74.93,85.47 76.45,87 76.45,95.2 72.26,99.39 72.26,112.52 JMP42.2
RESET_N_LS: length 12.3
  L3_SIG2 w0.152: JMP42.1 71.25,102.8 v1(73.15,100.89)
  BOTTOM w0.254: U36.3 v1(73.15,100.89)
RX_LOS: length 24.1
  L3_SIG2 w0.152: v1(46.7,29) 47.15,28.54 47.15,27.47 45.59,25.91 41.69,25.91 39.15,28.45 36.07,28.45 35.67,28.05 32.18,28.05 30.23,30.01 30.23,31.37 29.67,31.93 v1(29.04,31.93)
RX_LOS_B:
  vias: v1(46.7,30.14)
RX_LOS_C:
  vias: v1(46.7,32.6)
RX_LOS_L:
  vias: v1(46.7,34.7)
RXCTRL_0_LS: length 53.5
  TOP w0.254: U64.8 v1(116.22,22.91)
  L14_SIG3 w0.152: v1(116.22,22.91) 116.59,22.54 116.59,17.91 118.19,16.31 118.19,9.34 116.27,7.42 103.81,7.42 102.79,6.4 95.19,6.4 93.46,8.13 89.53,8.13 v1(84.33,13.34)
RXCTRL_1_LS: length 58
  TOP w0.254: U64.9 v1(116.22,23.56)
  L14_SIG3 w0.152: v1(116.22,23.56) 117.47,22.3 117.47,17.91 118.64,16.74 118.64,9.15 115.44,5.94 95,5.94 94.01,6.93 89.08,6.93 82.55,13.46 v1(81.66,13.46)
SEC_EN: length 3.4
  BOTTOM w0.254: R788.2 14.42,130.37 R791.2 ; R788.2 v1(14.41,131.9) ; R788.2 R790.1
SEC_LED:
  vias: v1(14.61,136.97)
SEC_OSC_EN: length 229
  TOP w0.254: v1(14.41,129.24) 13.57,128.4 11.05,128.4 10.41,129.03 v1(10.41,133.6) ; v1(102.49,17.65) 101.98,17.65 101.32,18.31 U42.7
  L3_SIG2 w0.152: v1(19.05,119.37) 18.42,118.75 14.48,118.75 12.57,120.65 12.57,127.4 v1(14.41,129.24)
  L14_SIG3 w0.152: v1(19.05,119.37) 19.57,119.37 28.96,109.98 28.96,105.66 31.21,103.41 49.12,103.41 51.94,100.58 51.94,90.93 59.31,83.57 59.31,71.63 59.36,71.58 59.36,59.59 59.44,59.52 59.44,59.05 69.6,48.9 74.3,48.9 77.72,45.47 77.72,29.46 79.48,27.71 96.06,27.71 96.98,26.8 96.98,23.86 97.23,23.61 101.01,23.61 101.75,22.88 101.75,18.39 v1(102.49,17.65)
  BOTTOM w0.254: v1(10.41,133.6) 9.14,133.6 8.64,134.11 8.64,154.05 6.99,155.7 6.99,162.56 9.14,164.72 11.56,164.72 12.45,165.61 v1(12.45,166.8)
SEC_REFP: length 5.2
  TOP w0.254: U100.11 13.6,141 12.55,139.95 v1(12.55,137.3)
SEC_STDBY: length 3.5
  BOTTOM w0.254: R789.2 11.53,134.75 R793.1 v1(11.55,136) R794.2
SI_MODE0: length 27.9
  TOP w0.254: v1(12.7,146.56) 13.66,146.56 14.22,146 U100.1 ; SW16.3 v1(2.67,165.35)
  L3_SIG2 w0.152: v1(2.67,165.35) 4.45,163.58 4.45,160.15 12.06,152.53 12.06,147.83 12.7,147.19 v1(12.7,146.56)
  BOTTOM w0.254: R715.2 v1(12.7,146.56) ; R721.2 v1(2.67,165.35)
SI_MODE1: length 37.9
  TOP w0.254: U100.47 v1(15.91,145.84) ; 3.94,164.2 v1(3.94,165.35)
  L3_SIG2 w0.152: v1(15.91,145.84) 15.61,146.15 15.4,146.15 13.59,147.96 13.59,152.27 5.71,160.15 5.71,163.58 v1(3.94,165.35)
  BOTTOM w0.254: R722.2 v1(3.94,165.35) ; R716.2 14.92,155.44 14.49,155 14.49,149.73 15.91,148.31 v1(15.91,145.84)
SPI_CLK: length 150.7
  TOP w0.254: J101.36 v1(29.98,10.67)
  L3_SIG2 w0.152: v1(8.26,121.67) 6.49,119.9 6.49,118.12 6.48,118.11 6.48,109.6 6.6,109.47 6.6,31.37 5.08,29.84 5.08,26.16 7.11,24.13 7.11,6.99 12.57,1.52 26.95,1.52 29.98,4.56 v1(29.98,10.67)
SPI_CLK_SOURCE/PIN4: length 1.9
  BOTTOM w0.254: R763.2 7.42,122.81 R768.2 9.26,122.81 R757.1
SPI_LE1: length 145.3
  TOP w0.254: J101.34 v1(28.98,10.67)
  L3_SIG2 w0.152: v1(28.98,10.67) 28.98,4.21 26.8,2.03 13.08,2.03 8.38,6.73 8.38,24.38 9.07,25.07 9.07,107.77 6.95,109.89 6.95,117.84 v1(8.27,119.16)
SPI_LE1_SOURCE/PIN3: length 1.9
  BOTTOM w0.254: R762.2 R767.2 R756.1
SPI_LE2: length 150.5
  TOP w0.254: J101.39 v1(31.98,3.61)
  L3_SIG2 w0.152: v1(8.27,124.24) 7.15,124.24 5.97,123.07 5.97,31.39 4.62,30.03 4.62,25.73 6.6,23.75 6.6,6.85 12.43,1.02 27.18,1.02 29.77,3.61 v1(31.98,3.61)
SPI_LE2_SOURCE: length 1.8
  BOTTOM w0.254: R758.1 R769.2 R764.2
SPI_MISO: length 140.7
  TOP w0.254: J101.40 v1(31.98,10.67)
  L3_SIG2 w0.152: v1(31.98,10.67) 30.63,12.01 28.77,12.01 27.86,11.11 27.86,5.13 27.17,4.44 27.17,4.4 25.92,3.15 17.93,3.15 10.09,10.99 10.09,22.98 10.29,23.17 10.29,114.05 8.29,116.04 v1(8.29,116.58)
SPI_MISO_SOURCE/PIN2: length 1.8
  BOTTOM w0.254: R755.1 R766.2 8.22,117.77 R761.2
SPI_MOSI: length 138.7
  TOP w0.254: J101.38 v1(30.98,10.67)
  L3_SIG2 w0.152: v1(8.27,114.08) 9.53,112.83 9.53,15.77 9.21,15.45 9.21,10.22 16.89,2.54 26.54,2.54 28.32,4.32 28.32,10.92 28.96,11.56 30.09,11.56 v1(30.98,10.67)
SPI_MOSI_SOURCE/PIN1: length 1.8
  BOTTOM w0.254: R760.2 R765.2 R754.1
ST/GPI1: length 147.9
  TOP w0.254: v1(108.2,10.16) SW11.5
  L3_SIG2 w0.152: v1(108.2,10.16) 108.78,10.73 108.78,12.13 106.87,14.03 106.87,29.53 107.7,30.35 107.7,32.38 106.3,33.78 106.3,42.55 96.95,51.89 96.95,70.31 88.52,78.74 43.92,78.74 43.5,79.16 v2(43.09,79.16)
  BOTTOM w0.254: R461.1 119.63,20.83 120.6,19.86 120.6,16.64 118.97,15.01 109.37,15.01 108.84,14.48 108.84,13.65 108.27,13.08 ; 108.27,13.08 108.27,12.38 108.84,11.81 108.84,10.73 108.27,10.16 v1(108.2,10.16) ; 108.27,13.08 R617.1
STATUS0: length 4.2
  TOP w0.254: U100.46 16.41,149.32 16.38,149.35 R704.1 R712.1
STATUS0_G: length 55.8
  L3_SIG2 w0.152: v1(16.38,151) 15.75,150.37 15.75,147.31 16.51,146.55 16.51,145.54 16.21,145.24 16.21,143.31 16.38,143.13 16.38,140.97 13.21,137.79 13.21,134.11 11.56,132.46 11.56,120.78 11.43,120.65 11.43,119.63 13.97,117.09 13.97,114.17 20.45,107.7 22.7,107.7 24.99,109.99 v1(24.99,110.42)
STATUS1/PIN0: length 72.6
  TOP w0.254: v1(17.53,149.86) 17.53,148.97 17.25,148.7 17.24,148.7 16.91,148.37 U100.45
  L3_SIG2 w0.152: v1(23.01,108.66) 14.43,117.24 14.43,117.28 12.06,119.65 12.06,132.21 13.67,133.81 13.67,136.86 17.07,140.26 17.07,144.7 17.78,145.41 17.78,146.05 16.46,147.37 16.46,148.79 v1(17.53,149.86)
  L14_SIG3 w0.152: v1(7.38,112.69) 18.98,112.69 v1(23.01,108.66)
  BOTTOM w0.254: R709.2 21.29,108.44 R706.2 22.3,108.45 22.51,108.66 v1(23.01,108.66)
STATUS1_B: length 1.3
  BOTTOM w0.254: U106.4 R709.1
SYNCN: length 72.5
  TOP w0.254: U100.42 18.41,148.08 v1(18.41,148.08)
  L3_SIG2 w0.152: v1(18.41,148.08) 20.7,145.8 25.53,145.8 26.8,144.53 29.34,144.53 33.91,139.95 33.91,121.41 37.85,117.47 50.67,117.47 52.55,115.6 v1(52.55,112.5) v1(52.55,110.6)
  BOTTOM w0.254: R719.2 18.67,155.42 18.24,154.99 18.24,152.83 18.41,152.65 v1(18.41,148.08)
SYNCN_/RST: length 8.1
  TOP w0.254: v1(49.46,110.57) 50.85,110.57 51.18,110.24 51.18,107.41 v1(52.57,106.03)
  BOTTOM w0.254: R736.2 50.84,110.57 v1(49.46,110.57)
SYNCN_/RST_B: length 1.3
  BOTTOM w0.254: R738.1 U111.6
SYNCN_PB: length 6.4
  TOP w0.254: SW14.1 46.43,113.65 47.06,113.02 v1(47.06,112.47)
  BOTTOM w0.254: v1(47.06,112.47) 45.53,112.47 R734.1 R735.1
SYNCN_RST: length 8.3
  TOP w0.254: v1(52.57,107.93) 51.94,108.55 51.94,111.76 51.23,112.47 v1(49.46,112.47)
  BOTTOM w0.254: v1(49.46,112.47) 50.84,112.47 R737.2
SYNCN_RST_B: length 1.3
  BOTTOM w0.254: R739.1 U111.4
TCK: length 66.2
  TOP w0.254: U40.7 v1(52.29,15.88)
  L14_SIG3 w0.152: v2(44.09,71.16) 43.54,70.61 42.93,70.61 42.69,70.37 42.69,56.91 41.27,55.5 41.27,23.61 44.18,20.7 50.27,20.7 52.29,18.67 v1(52.29,15.88)
TCK_LS: length 6.2
  TOP w0.254: JMP47.9 50.67,7.24 51.94,7.24 52.29,7.59 U40.14
TDI: length 65.5
  TOP w0.254: U40.5 v1(53.59,15.88)
  L14_SIG3 w0.152: v1(53.59,15.88) 53.59,16.89 53.98,17.27 53.98,18.8 51.05,21.72 44.58,21.72 42.29,24 42.29,54.99 44.55,57.25 44.55,69.7 v2(44.09,70.16)
TDI_LS: length 3.9
  TOP w0.254: U40.16 JMP47.5
TDO: length 66.1
  TOP w0.254: U40.4 v1(54.24,16.52)
  L14_SIG3 w0.152: v1(54.24,16.52) 54.24,16.78 54.48,17.02 54.48,19.18 50.55,23.11 44.45,23.11 43.23,24.33 43.23,54.79 45.59,57.15 45.59,70.66 v2(46.09,71.16)
TDO_LS: length 4.7
  TOP w0.254: U40.17 54.24,6.97 JMP47.3
TESTEN: length 129.1
  TOP w0.254: v1(112.01,10.16) SW11.11
  L3_SIG2 w0.152: v2(42.09,78.16) 42.66,77.6 88.15,77.6 95.68,70.06 95.68,52.04 105.79,41.93 105.79,33.53 107.12,32.19 107.12,30.54 106.41,29.83 106.41,12.72 107.44,11.68 107.44,10.31 108.05,9.7 109.68,9.7 110.56,10.59 111.58,10.59 v1(112.01,10.16)
TMS: length 64.4
  TOP w0.254: U40.6 v1(52.94,16.52)
  L14_SIG3 w0.152: v1(52.94,16.52) 52.94,17 53.47,17.53 53.47,18.54 50.8,21.21 44.32,21.21 41.78,23.75 41.78,55.24 43.69,57.15 43.69,67.99 43.69,67.99 43.69,68.75 v2(44.09,69.16)
TMS_LS: length 4.7
  TOP w0.254: U40.15 52.94,6.97 JMP47.7
TRST_N: length 67
  TOP w0.254: U40.3 v1(54.89,15.88)
  L14_SIG3 w0.152: v1(54.89,15.88) 54.89,16.67 54.94,16.71 54.94,20.75 50.41,25.27 44.6,25.27 43.69,26.19 43.69,54.23 46.61,57.15 46.61,71.67 v2(47.09,72.16)
TRST_N_LS: length 6.2
  TOP w0.254: U40.18 54.89,7.59 55.24,7.24 56.52,7.24 JMP47.1
TX_DISABLE: length 33.7
  L3_SIG2 w0.152: v1(46.7,17.29) v1(44.8,17.29)
  L14_SIG3 w0.152: v1(29.04,35.93) 36.02,35.93 36.42,36.32 39.48,36.32 40.51,35.29 40.51,23.24 44.32,19.43 44.32,17.76 v1(44.8,17.29)
TX_DISABLE_/RST: length 37.1
  L14_SIG3 w0.152: v1(50.49,31.06) 51.05,31.63 54.48,31.63 56.26,29.84 56.26,13.97 55.37,13.08 50.29,13.08 46.26,17.11 46.26,17.5 v1(44.8,18.97)
TX_DISABLE_/RST_B:
  vias: v1(44.8,20.11)
TX_DISABLE_/RST_C:
  vias: v1(44.8,22.56)
TX_DISABLE_/RST_L:
  vias: v1(44.8,24.66)
TX_DISABLE_RST: length 27.9
  L14_SIG3 w0.152: v1(46.7,18.97) 50.42,15.24 54.9,15.24 55.5,15.84 55.5,29.31 53.75,31.06 v1(52.38,31.06)
TX_DISABLE_RST_B:
  vias: v1(46.7,20.11)
TX_DISABLE_RST_C:
  vias: v1(46.7,22.56)
TX_DISABLE_RST_L:
  vias: v1(46.7,24.66)
TX_FAULT: length 21.4
  L3_SIG2 w0.152: v1(44.8,29) 43.97,29.83 43.97,34.01 41.25,36.73 v1(29.04,36.73)
TX_FAULT_B:
  vias: v1(44.8,30.14)
TX_FAULT_C:
  vias: v1(44.8,32.6)
TX_FAULT_L:
  vias: v1(44.8,34.7)
USB_I2C_INT1: length 86.9
  TOP w0.254: J101.18 v1(20.98,10.67)
  L3_SIG2 w0.152: v1(20.98,10.67) 20.98,11.91 19.48,13.41 19.48,20.19 21.39,22.1 25.78,22.1 25.91,22.23 34.68,22.23 35.43,22.99 40.51,22.99 42.96,20.54 49.31,20.54 49.55,20.3 54.52,20.3 56.13,21.92 56.13,28.65 71.76,44.27 78.16,44.27 v1(78.61,43.81)
USB_I2C_RESET1: length 94.5
  TOP w0.254: J101.20 v1(21.98,10.67)
  L3_SIG2 w0.152: v1(83.57,43.81) 83.13,43.38 79.81,43.38 78.41,44.78 71.62,44.78 55.63,28.78 55.63,23.14 53.79,21.3 43.85,21.3 41.48,23.67 26.21,23.67 25.15,22.61 21.25,22.61 19.02,20.38 19.02,12.73 19.56,12.19 19.56,10.92 20.24,10.24 21.55,10.24 v1(21.98,10.67)
USB_I2C_SCL: length 97
  TOP w0.254: J101.22 v1(22.98,10.67)
  L3_SIG2 w0.152: v1(81.92,43.81) 79.93,45.8 71.18,45.8 54.61,29.22 54.61,24.74 53.04,23.17 44.77,23.17 43.36,24.59 25.6,24.59 24.64,23.62 20.98,23.62 17.55,20.19 17.55,10.8 19.02,9.32 21.93,9.32 22.98,10.37 v1(22.98,10.67)
USB_I2C_SDA: length 94.6
  TOP w0.254: J101.24 v1(23.98,10.67)
  L3_SIG2 w0.152: v1(23.98,10.67) 23.47,11.18 22.88,11.18 22.52,10.82 22.52,10.56 21.74,9.78 19.58,9.78 18.55,10.81 18.55,20.55 21.12,23.11 24.89,23.11 25.91,24.13 42.42,24.13 44.42,22.13 52.64,22.13 55.12,24.6 55.12,28.97 71.44,45.29 78.83,45.29 80.26,43.85 v1(80.26,43.81)
USB_INT2: length 94.7
  TOP w0.254: J101.21 v1(22.98,3.61)
  L3_SIG2 w0.152: v1(76.96,43.81) 71.95,43.81 56.64,28.51 56.64,21.78 54.42,19.56 46.36,19.56 46.18,19.74 45.57,19.74 45.39,19.56 43.18,19.56 40.21,22.53 35.74,22.53 34.98,21.77 26.22,21.77 25.97,21.52 21.46,21.52 19.94,20 19.94,13.84 21.59,12.19 23.5,12.19 24.41,11.28 24.41,6.25 22.98,4.82 v1(22.98,3.61)
USB_RESET2: length 91.7
  TOP w0.254: J101.23 v1(23.98,3.61)
  L3_SIG2 w0.152: v1(85.34,43.81) 85.8,43.36 85.8,40.36 83.03,37.59 70.99,37.59 60.71,27.3 60.71,17.17 55.93,12.4 48.31,12.4 47.45,13.26 29.88,13.26 29.25,12.63 27.83,12.63 27.41,12.2 27.41,7.98 23.98,4.55 v1(23.98,3.61)
VAC_REF_A: length 4.4
  TOP w0.254: v1(26.21,133.11) 26.92,133.82 v1(26.92,135.54)
  BOTTOM w0.254: U104.8 26.07,132.97 v1(26.21,133.11) ; C656.2 v1(26.92,135.54)
VAC_REF_B: length 4.4
  TOP w0.254: v1(23.37,163.07) 23.51,163.21 U105.8 ; C671.2 v1(20.93,162.36)
  BOTTOM w0.254: v1(20.93,162.36) 22.66,162.36 v1(23.37,163.07)

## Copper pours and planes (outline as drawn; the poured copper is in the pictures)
5V on TOP (solid shape): 111.9,149.8 107.91,149.8 107.91,152.22 111.9,152.22
5V on TOP (solid shape): 62.56,162.5 63.47,162.5 63.47,163.52 63.83,163.52 63.83,162.5 64.12,162.5 64.12,163.52 64.48,163.52 64.48,162.5 64.78,162.5 64.78,163.52 65.13,163.52 65.13,158.01 61.54,158.01 61.54,164.79 62.56,164.79
5V on TOP (solid shape): 66.11,152.07 63.83,152.07 63.83,151.16 64.84,151.16 64.84,150.8 63.83,150.8 63.83,150.51 64.84,150.51 64.84,150.15 63.83,150.15 63.83,149.85 64.84,149.85 64.84,149.5 59.33,149.5 59.33,153.09 66.11,153.09
5V on TOP (solid shape): 85.16,152.07 82.88,152.07 82.88,151.16 83.89,151.16 83.89,150.8 82.88,150.8 82.88,150.51 83.89,150.51 83.89,150.15 82.88,150.15 82.88,149.85 83.89,149.85 83.89,149.5 78.38,149.5 78.38,153.09 85.16,153.09
5V on TOP (solid shape): 90.12,33.09 91.03,33.09 91.03,34.11 91.39,34.11 91.39,33.09 91.68,33.09 91.68,34.11 92.04,34.11 92.04,33.09 92.33,33.09 92.33,34.11 92.69,34.11 92.69,28.6 89.1,28.6 89.1,35.38 90.12,35.38
5V on TOP (solid shape): 96.72,114.24 97.64,114.24 97.64,115.26 97.99,115.26 97.99,114.24 98.29,114.24 98.29,115.26 98.64,115.26 98.64,114.24 98.94,114.24 98.94,115.26 99.29,115.26 99.29,109.75 95.71,109.75 95.71,116.53 96.72,116.53
5V on TOP (solid shape): 109.93,114.24 110.85,114.24 110.85,115.26 111.2,115.26 111.2,114.24 111.5,114.24 111.5,115.26 111.85,115.26 111.85,114.24 112.15,114.24 112.15,115.26 112.5,115.26 112.5,109.75 108.92,109.75 108.92,116.53 109.93,116.53
5V on TOP (solid shape): 110.57,33.35 111.48,33.35 111.48,34.36 111.84,34.36 111.84,33.35 112.13,33.35 112.13,34.36 112.49,34.36 112.49,33.35 112.78,33.35 112.78,34.36 113.14,34.36 113.14,28.85 109.55,28.85 109.55,35.63 110.57,35.63
5V on TOP (solid shape): 112.6,76.91 113.51,76.91 113.51,77.92 113.87,77.92 113.87,76.91 114.16,76.91 114.16,77.92 114.52,77.92 114.52,76.91 114.81,76.91 114.81,77.92 115.17,77.92 115.17,72.42 111.58,72.42 111.58,79.19 112.6,79.19
5V on L10_PWR: 0.64,0.64 0.64,177.16 126.36,177.16 126.36,0.64 ; 4 cut-outs
DVDD on TOP (solid shape): 114.94,46.86 113.03,46.86 113.03,48.64 114.94,48.64
DVDD on L12_PWR: 126.36,46.1 65.15,46.1 65.15,77.34 48.77,77.34 48.77,70.36 43.43,70.36 43.43,76.45 37.85,76.45 37.85,84.71 126.36,84.71
GND on TOP (solid shape): 5,101.54 0,101.54 0,107.84 5,107.84
GND on TOP (solid shape): 5,93.84 0,93.84 0,100.14 5,100.14
GND on TOP (solid shape): 5,86.3 0,86.3 0,92.6 5,92.6
GND on TOP (solid shape): 5,78.6 0,78.6 0,84.9 5,84.9
GND on TOP (solid shape): 5,71.06 0,71.06 0,77.36 5,77.36
GND on TOP (solid shape): 5,63.36 0,63.36 0,69.66 5,69.66
GND on TOP (solid shape): 5,55.82 0,55.82 0,62.12 5,62.12
GND on TOP (solid shape): 5,48.12 0,48.12 0,54.42 5,54.42
GND on TOP (solid shape): 61.72,131.19 59.94,131.19 59.94,133.48 61.72,133.48
GND on TOP (solid shape): 64.01,131.19 62.23,131.19 62.23,133.48 64.01,133.48
GND on TOP (solid shape): 66.29,131.19 64.52,131.19 64.52,132.46 66.29,132.46
GND on TOP (solid shape): 69.34,131.19 67.56,131.19 67.56,133.48 69.34,133.48
GND on TOP (solid shape): 71.63,131.19 69.85,131.19 69.85,133.48 71.63,133.48
GND on TOP (solid shape): 73.91,131.19 72.14,131.19 72.14,132.46 73.91,132.46
GND on TOP (solid shape): 77.09,131.19 75.31,131.19 75.31,133.48 77.09,133.48
GND on TOP (solid shape): 79.38,131.19 77.6,131.19 77.6,133.48 79.38,133.48
GND on TOP (solid shape): 81.66,131.19 79.88,131.19 79.88,132.46 81.66,132.46
GND on TOP (solid shape): 85.09,131.32 83.31,131.32 83.31,133.6 85.09,133.6
GND on TOP (solid shape): 87.38,131.32 85.6,131.32 85.6,133.6 87.38,133.6
GND on TOP (solid shape): 89.66,131.32 87.88,131.32 87.88,132.59 89.66,132.59
GND on TOP (solid shape): 93.47,131.32 91.69,131.32 91.69,133.6 93.47,133.6
GND on TOP (solid shape): 95.76,131.32 93.98,131.32 93.98,133.6 95.76,133.6
GND on TOP (solid shape): 98.04,131.32 96.27,131.32 96.27,132.59 98.04,132.59
GND on TOP (solid shape): 99.57,81.53 98.3,81.53 98.3,83.31 99.57,83.31
GND on TOP (solid shape): 100.58,86.11 98.3,86.11 98.3,87.88 100.58,87.88
GND on TOP (solid shape): 100.58,83.82 98.3,83.82 98.3,85.6 100.58,85.6
GND on TOP (solid shape): 102.23,29.84 100.46,29.84 100.46,32.13 102.23,32.13
GND on TOP (solid shape): 104.52,29.84 102.74,29.84 102.74,32.13 104.52,32.13
GND on TOP (solid shape): 106.81,29.84 105.03,29.84 105.03,31.11 106.81,31.11
GND on TOP (solid shape): 120.52,131.57 119.25,131.57 119.25,133.35 120.52,133.35
GND on TOP (solid shape): 120.52,129.29 118.24,129.29 118.24,131.06 120.52,131.06
GND on TOP (solid shape): 120.52,127 118.24,127 118.24,128.78 120.52,128.78
GND on TOP (solid shape): 121.16,51.44 119.89,51.44 119.89,53.21 121.16,53.21
GND on TOP (solid shape): 121.16,49.15 118.87,49.15 118.87,50.93 121.16,50.93
GND on TOP (solid shape): 121.16,46.86 118.87,46.86 118.87,48.64 121.16,48.64
GND on TOP (solid shape): 3.19,137.13 4.19,132.76 5.19,137.13 5.19,140.06 8.19,140.06 8.19,131.06 0.19,131.06 0.19,140.06 3.19,140.06
GND on TOP (solid shape): 8.19,144.48 5.19,144.48 5.19,147.41 4.19,151.78 3.19,147.41 3.19,144.48 0.19,144.48 0.19,153.48 8.19,153.48
GND on TOP (solid shape): 24.33,53.54 25.33,49.17 26.33,53.54 26.33,56.47 29.33,56.47 29.33,47.47 21.33,47.47 21.33,56.47 24.33,56.47
GND on TOP (solid shape): 30.91,90.21 27.91,90.21 27.91,93.14 26.91,97.51 25.91,93.14 25.91,90.21 22.91,90.21 22.91,99.21 30.91,99.21
GND on TOP (solid shape): 34.49,51 35.49,46.63 36.49,51 36.49,53.93 39.49,53.93 39.49,44.93 31.49,44.93 31.49,53.93 34.49,53.93
GND on TOP (solid shape): 42.34,92.75 39.34,92.75 39.34,95.68 38.34,100.05 37.34,95.68 37.34,92.75 34.34,92.75 34.34,101.75 42.34,101.75
GND on TOP (solid shape): 47.19,51 48.19,46.63 49.19,51 49.19,53.93 52.19,53.93 52.19,44.93 44.19,44.93 44.19,53.93 47.19,53.93
GND on TOP (solid shape): 51.23,92.75 48.23,92.75 48.23,95.68 47.23,100.05 46.23,95.68 46.23,92.75 43.23,92.75 43.23,101.75 51.23,101.75
GND on TOP (solid shape): 57.35,51 58.35,46.63 59.35,51 59.35,53.93 62.35,53.93 62.35,44.93 54.35,44.93 54.35,53.93 57.35,53.93
GND on TOP (solid shape): 60.12,90.21 57.12,90.21 57.12,93.14 56.12,97.51 55.12,93.14 55.12,90.21 52.12,90.21 52.12,99.21 60.12,99.21
GND on L2_GND, L4_GND, L6_GND, L7_GND, L9_GND, L11_GND, L13_GND, L15_GND: 0,47.62 0,108.33 0.64,108.33 0.64,177.16 126.36,177.16 126.36,0.64 0.64,0.64 0.64,47.62
GND on L3_SIG2: 0,54.18 0,105.69 4.98,105.69 4.98,54.18
GND_CAGE on TOP (solid shape): 40.09,33.23 39.04,33.23 39.04,35.19 40.09,35.19
GND_CAGE on TOP (solid shape): 40.06,38.02 39.05,38.02 39.04,38.03 39.04,40.21 24.58,40.21 24.58,28.02 39.01,28.02 39.04,28.05 39.04,30.4 40.12,30.4 40.12,26 -2.26,26 -2.26,42.26 40.06,42.26
VDDA on TOP (solid shape): 102.23,36.07 100.46,36.07 100.46,37.97 102.23,37.97
VDDA on L12_PWR: 126.36,45.47 64.52,45.47 64.52,76.83 49.4,76.83 49.4,69.72 42.8,69.72 42.8,75.82 37.85,75.82 37.85,29.97 126.36,29.97
VDDD on TOP (solid shape): 106.43,86.11 104.52,86.11 104.52,87.88 106.43,87.88
VDDD on L5_PWR: 43.56,75.69 47.24,75.69 47.24,70.99 99.95,70.99 99.95,87.88 126.36,87.88 126.36,50.16 43.56,50.16 43.56,72.39 43.94,72.39 43.94,74.04 43.56,74.04
VDDO on TOP (solid shape): 61.72,137.54 59.94,137.54 59.94,139.45 61.72,139.45
VDDO on L8_PWR: 66.93,177.16 66.93,123.83 30.73,123.83 30.73,69.98 43.18,69.98 43.18,78.61 48.01,78.61 48.01,44.32 0.63,44.32 0.64,177.16
VDDO on L12_PWR: 126.36,29.34 37.08,29.34 37.08,85.34 126.36,85.34 126.36,104.01 0.64,104.01 0.64,0.64 126.36,0.64
VDDRA_HS on TOP (solid shape): 69.34,137.54 67.56,137.54 67.56,139.45 69.34,139.45
VDDRA_HS on L8_PWR: 67.56,177.16 76.96,177.16 76.96,116.84 36.45,116.84 36.45,74.3 42.55,74.3 42.55,70.61 31.37,70.61 31.37,123.19 67.56,123.19
VDDRA_LS on TOP (solid shape): 93.34,137.54 91.57,137.54 91.57,139.45 93.34,139.45
VDDRA_LS on L8_PWR: 48.51,44.32 48.51,74.17 65.28,74.17 65.28,96.77 95,96.77 95,160.66 86.87,160.66 86.87,177.16 126.36,177.16 126.36,44.32
VDDRB_HS on TOP (solid shape): 77.09,137.54 75.31,137.54 75.31,139.45 77.09,139.45
